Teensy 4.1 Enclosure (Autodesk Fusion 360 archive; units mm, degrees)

design "Teensy 4.1 Enclosure" references "Teensy 4.1 Modell"
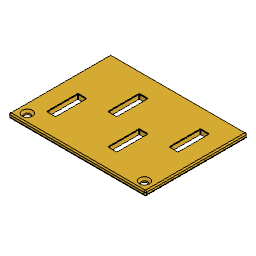
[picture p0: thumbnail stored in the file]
description: STEP AP214
part number: Teensy_4.1_Assembly_simplified
parameter "adsk_nheig" = 1.8
parameter "adsk_maxdia" = 6.3525
parameter "adsk_nomdia" = 3
parameter "adsk_waflat" = 5.5
parameter "adsk_chamang1" = 30
parameter "adsk_chamang2" = 30
parameter "adsk_beardia" = 5.39
parameter "adsk_nheig_1" = 1.8
parameter "adsk_maxdia_1" = 6.3525
parameter "adsk_nomdia_1" = 3
parameter "adsk_waflat_1" = 5.5
parameter "adsk_chamang1_1" = 30
parameter "adsk_chamang2_1" = 30
parameter "adsk_beardia_1" = 5.39
external_derived "Extern abgeleitet" bodies "Teensy 4.1"
move "Verschieben2"
move "Verschieben3" TranslateX 0 TranslateY 24 TranslateZ 3
sketch "Skizze6" plane through (0, 0, 0) normal (0, 0, 1) x axis (1, 0, 0)
  line L1 (65, 50) -> (-2, 50)
  line L2 (65, 0) -> (65, 50)
  line L3 (-2, 0) -> (65, 0)
  line L4 (-2, 50) -> (-2, 0)
  horizontal L1
  vertical L2
  horizontal L3
  vertical L4
extrude "Extrusion4" new body sketch "Skizze6" along normal blind 12
fillet "Abrundung4" radius 0.6
work_plane "Arbeitsebene" AlongDistance -2.5
split "Teilen"
shell "Schale" innerThickness 2
fillet "Abrundung5" radius 0.5
sketch "Skizze7" plane through (65, 0, 0) normal (1, 0, 0) x axis (0, 1, 0)
  line L1 (0.6, 9.5) -> (49.4, 9.5)
  line L2 (0.6, 0.6) -> (0.6, 9.5)
  line L3 (49.4, 0.6) -> (0.6, 0.6)
  line L4 (49.4, 9.5) -> (49.4, 0.6)
  line L5 (43.7841, 7.2878) -> (29.7841, 7.2878)
  line L6 (43.7841, 4.2878) -> (43.7841, 7.2878)
  line L7 (29.7841, 4.2878) -> (43.7841, 4.2878)
  line L8 (29.7841, 7.2878) -> (29.7841, 4.2878)
  horizontal L5
  vertical L6
  horizontal L7
  vertical L8
sketch "Skizze8" plane through (65, 0, 0) normal (1, 0, 0) x axis (0, 1, 0)
  line L1 (0.6, 9.5) -> (49.4, 9.5)
  line L2 (0.6, 0.6) -> (0.6, 9.5)
  line L3 (49.4, 0.6) -> (0.6, 0.6)
  line L4 (49.4, 9.5) -> (49.4, 0.6)
  line L5 (44.2751, 7.4459) -> (29.7875, 7.4459)
  line L6 (44.2751, 4.2911) -> (44.2751, 7.4459)
  line L7 (29.7875, 4.2911) -> (44.2751, 4.2911)
  line L8 (29.7875, 7.4459) -> (29.7875, 4.2911)
  horizontal L5
  vertical L6
  horizontal L7
  vertical L8
extrude "Extrusion6" cut sketch "Skizze8" profile of L5 L6 L7 L8 against normal blind 3
fillet "Abrundung7" radius 0.2
sketch "Skizze9" plane through (-2, 0, 0) normal (-1, 0, 0) x axis (0, -1, 0)
  line L1 (-50, 9.5) -> (-0.6, 9.5)
  line L2 (-50, 0.6) -> (-50, 9.5)
  line L3 (-0.6, 0.6) -> (-50, 0.6)
  line L4 (-0.6, 9.5) -> (-0.6, 0.6)
  line L5 (-31.9719, 7.9619) -> (-41.6044, 7.9619)
  line L6 (-31.9719, 3.7343) -> (-31.9719, 7.9619)
  line L7 (-41.6044, 3.7343) -> (-31.9719, 3.7343)
  line L8 (-41.6044, 7.9619) -> (-41.6044, 3.7343)
  horizontal L5
  vertical L6
  horizontal L7
  vertical L8
extrude "Extrusion7" cut sketch "Skizze9" profile of L5 L6 L7 L8 against normal blind 3
fillet "Abrundung8" radius 0.2
move "Verschieben4" TranslateX 0 TranslateY 0 TranslateZ -0.8
combine "Kombinieren2"
sketch "Skizze10" plane through (0, 0, 9.5) normal (0, 0, 1) x axis (-1, 0, 0)
  line L1 (-62.5, -48.5) -> (-0.5, -48.5)
  line L2 (-63.5, -2.5) -> (-63.5, -47.5)
  line L3 (-0.5, -1.5) -> (-62.5, -1.5)
  line L4 (0.5, -47.5) -> (0.5, -2.5)
  line L5 (1.8, -0.6) -> (1.8, -49.8)
  line L6 (-64.4, -0.2) -> (1.4, -0.2)
  line L7 (-64.8, -49.4) -> (-64.8, -0.6)
  line L8 (1.8, -49.8) -> (-64.4, -49.8)
  line L9 (0.5, -1.5) -> (-8.0206, -1.5)
  line L10 (0.5, -8.5367) -> (0.5, -1.5)
  line L11 (-8.0206, -8.5367) -> (0.5, -8.5367)
  line L12 (-8.0206, -1.5) -> (-8.0206, -8.5367)
  line L13 (-63.5206, -8.5367) -> (-55, -8.5367)
  line L14 (-63.5206, -1.5) -> (-63.5206, -8.5367)
  line L15 (-55, -1.5) -> (-63.5206, -1.5)
  line L16 (-55, -8.5367) -> (-55, -1.5)
  arc A1 centre (-0.5, -47.5) radius 1 clockwise from (0.5, -47.5) to (-0.5, -48.5)
  arc A2 centre (-62.5, -47.5) radius 1 clockwise from (-62.5, -48.5) to (-63.5, -47.5)
  arc A3 centre (-62.5, -2.5) radius 1 clockwise from (-63.5, -2.5) to (-62.5, -1.5)
  arc A4 centre (-0.5, -2.5) radius 1 clockwise from (-0.5, -1.5) to (0.5, -2.5)
  arc A5 centre (1.4, -0.6) radius 0.4 clockwise from (1.4, -0.2) to (1.8, -0.6)
  arc A6 centre (-64.4, -0.6) radius 0.4 clockwise from (-64.8, -0.6) to (-64.4, -0.2)
  arc A7 centre (-64.4, -49.4) radius 0.4 clockwise from (-64.4, -49.8) to (-64.8, -49.4)
  point P26 (0.5, -8.5367)
  point P24 (-8.0206, -1.5)
  horizontal L9
  vertical L10
  horizontal L11
  vertical L12
  coincident L4 P26
  coincident L3 P24
  horizontal L15
  vertical L16
  horizontal L13
  vertical L14
extrude "Extrusion8" add sketch "Skizze10" profile of L2 A3 L3 A4 L4 L9 L10 L11 L12 L13 L15 L16 against normal blind 9.2
fillet "Abrundung9" radius 0.2
hole "Bohrung2" HoleDepth 15 HoleDiameter 3 TipAngle 180 CSDiameter 6 CSAngle 90 RefDim1 5 RefDim2 4
hole "Bohrung3" HoleDepth 15 HoleDiameter 3 TipAngle 180 CSDiameter 6 CSAngle 90 RefDim1 4 RefDim2 5
sketch "Skizze12" plane through (0, 0, 0) normal (0, 0, -1) x axis (1, 0, 0)
  line L1 (-1.4, -0.6) -> (64.4, -0.6)
  line L2 (-1.4, -49.4) -> (-1.4, -0.6)
  line L3 (64.4, -49.4) -> (-1.4, -49.4)
  line L4 (64.4, -0.6) -> (64.4, -49.4)
  line L5 (60.1995, -7.5699) -> (57.3998, -5.9529)
  line L6 (62.9998, -5.9537) -> (60.1995, -7.5699)
  line L7 (63.0002, -2.7206) -> (62.9998, -5.9537)
  line L8 (60.2005, -1.1036) -> (63.0002, -2.7206)
  line L9 (57.4002, -2.7197) -> (60.2005, -1.1036)
  line L10 (57.3998, -5.9529) -> (57.4002, -2.7197)
  circle C1 centre (60.2, -4.3367) radius 1.5
  circle C2 centre (2.8206, -4.3367) radius 1.5
  point P2 (60.2, -4.3367)
  point P14 (60.2, -4.3367)
  coincident P2 P14
  dimension "d77" distance P14 L10 = 2.8
extrude "Extrusion9" cut sketch "Skizze12" profile of C1 L5 L6 L7 L8 L9 L10 against normal blind 2.4
sketch "Skizze13" plane through (0, 0, 0) normal (0, 0, -1) x axis (1, 0, 0)
  line L1 (57.3998, -5.9529) -> (60.1995, -7.5699)
  line L2 (57.4002, -2.7197) -> (57.3998, -5.9529)
  line L3 (60.2005, -1.1036) -> (57.4002, -2.7197)
  line L4 (63.0002, -2.7206) -> (60.2005, -1.1036)
  line L5 (62.9998, -5.9537) -> (63.0002, -2.7206)
  line L6 (60.1995, -7.5699) -> (62.9998, -5.9537)
  line L7 (-1.4, -0.6) -> (64.4, -0.6)
  line L8 (-1.4, -49.4) -> (-1.4, -0.6)
  line L9 (64.4, -49.4) -> (-1.4, -49.4)
  line L10 (64.4, -0.6) -> (64.4, -49.4)
  line L11 (0.0214, -5.9546) -> (0.0199, -2.7214)
  line L12 (2.8221, -7.5699) -> (0.0214, -5.9546)
  line L13 (5.6214, -5.952) -> (2.8221, -7.5699)
  line L14 (5.6199, -2.7189) -> (5.6214, -5.952)
  line L15 (2.8192, -1.1036) -> (5.6199, -2.7189)
  line L16 (0.0199, -2.7214) -> (2.8192, -1.1036)
  circle C1 centre (2.8206, -4.3367) radius 1.5
  point P8 (2.8206, -4.3367)
  point P19 (2.8206, -4.3367)
  coincident P8 P19
  dimension "d80" distance P19 L16 = 2.8
extrude "Extrusion10" cut sketch "Skizze13" profile of C1 L11 L12 L13 L14 L15 L16 against normal blind 2.4
delete_face "Fläche löschen1"
delete_face "Fläche löschen2"
fillet "Abrundung10" radius 0.1
fillet "Abrundung11" radius 0.1
sketch "Skizze14" plane through (0, 0, 2) normal (0, 0, 1) x axis (-1, 0, 0)
  line L1 (-8.2206, -2.5) -> (-8.2206, -8.3367)
  line L2 (-54.8, -2.5) -> (-8.2206, -2.5)
  line L3 (-54.8, -8.3367) -> (-54.8, -2.5)
  line L4 (-62.5, -8.7367) -> (-55.2, -8.7367)
  line L5 (-62.5, -47.5) -> (-62.5, -8.7367)
  line L6 (-0.5, -47.5) -> (-62.5, -47.5)
  line L7 (-0.5, -8.7367) -> (-0.5, -47.5)
  line L8 (-7.8206, -8.7367) -> (-0.5, -8.7367)
  line L9 (-1, -27) -> (-62, -27)
  line L10 (-1, -30) -> (-1, -27)
  line L11 (-62, -30) -> (-1, -30)
  line L12 (-62, -27) -> (-62, -30)
  line L13 (-1, -46.6249) -> (-62, -46.6249)
  line L14 (-1, -44) -> (-1, -46.6249)
  line L15 (-62, -44) -> (-1, -44)
  line L16 (-62, -46.6249) -> (-62, -44)
  arc A1 centre (-55.2, -8.3367) radius 0.4 clockwise from (-54.8, -8.3367) to (-55.2, -8.7367)
  arc A2 centre (-7.8206, -8.3367) radius 0.4 clockwise from (-7.8206, -8.7367) to (-8.2206, -8.3367)
  horizontal L9
  vertical L10
  horizontal L11
  vertical L12
  horizontal L13
  vertical L14
  horizontal L15
  vertical L16
extrude "Extrusion11" new body sketch "Skizze14" profile of L9 L10 L11 L12 L13 L14 L15 L16 along normal blind 1
fillet "Abrundung12" radius 0.1
sketch "Skizze15" plane through (0, 0, 2) normal (0, 0, 1) x axis (-1, 0, 0)
  line L1 (-8.2206, -2.5) -> (-8.2206, -8.3367)
  line L2 (-54.8, -2.5) -> (-8.2206, -2.5)
  line L3 (-54.8, -8.3367) -> (-54.8, -2.5)
  line L4 (-62.5, -8.7367) -> (-55.2, -8.7367)
  line L5 (-62.5, -47.5) -> (-62.5, -8.7367)
  line L6 (-0.5, -47.5) -> (-62.5, -47.5)
  line L7 (-0.5, -8.7367) -> (-0.5, -47.5)
  line L8 (-7.8206, -8.7367) -> (-0.5, -8.7367)
  curve K1
  curve K2
  curve K3
  curve K4
  arc A1 centre (-55.2, -8.3367) radius 0.4 clockwise from (-54.8, -8.3367) to (-55.2, -8.7367)
  arc A2 centre (-7.8206, -8.3367) radius 0.4 clockwise from (-7.8206, -8.7367) to (-8.2206, -8.3367)
  dimension "d92" Text1-Height = 4
  dimension "d93" Text = 0 (= "Text1-Text")
extrude "Extrusion12" add sketch "Skizze15" along normal blind 0.2
sketch "Skizze16" plane through (0, 0, 2.4) normal (0, 0, -1) x axis (1, 0, 0)
  line L1 (0.0199, -2.7214) -> (2.8192, -1.1036)
  line L2 (0.0214, -5.9546) -> (0.0199, -2.7214)
  line L3 (2.8221, -7.5699) -> (0.0214, -5.9546)
  line L4 (5.6214, -5.952) -> (2.8221, -7.5699)
  line L5 (5.6199, -2.7189) -> (5.6214, -5.952)
  line L6 (2.8192, -1.1036) -> (5.6199, -2.7189)
  circle C1 centre (2.8206, -4.3367) radius 1.5
  circle C2 centre (2.8206, -4.3367) radius 1.5
  concentric C1 C2
extrude "Extrusion13" cut sketch "Skizze16" profile of C1 C2 against normal blind 16
sketch "Skizze17" plane through (0, 0, 2.4) normal (0, 0, -1) x axis (1, 0, 0)
  line L1 (57.3998, -5.9529) -> (57.4002, -2.7197)
  line L2 (60.1995, -7.5699) -> (57.3998, -5.9529)
  line L3 (62.9998, -5.9537) -> (60.1995, -7.5699)
  line L4 (63.0002, -2.7206) -> (62.9998, -5.9537)
  line L5 (60.2005, -1.1036) -> (63.0002, -2.7206)
  line L6 (57.4002, -2.7197) -> (60.2005, -1.1036)
  circle C1 centre (60.2, -4.3367) radius 1.5
  circle C2 centre (60.2, -4.3367) radius 1.5
  concentric C1 C2
extrude "Extrusion14" cut sketch "Skizze17" profile of C1 C2 against normal blind 12
chamfer "Fase1" distance 1
chamfer "Fase2" distance 1
sketch "Skizze18" plane through (0, 0, 11.2) normal (0, 0, 1) x axis (-1, 0, 0)
  line L1 (-64.4, -49.4) -> (-64.4, -0.6)
  line L2 (1.4, -49.4) -> (-64.4, -49.4)
  line L3 (1.4, -0.6) -> (1.4, -49.4)
  line L4 (-64.4, -0.6) -> (1.4, -0.6)
  line L5 (-52, -25) -> (-56, -25)
  line L6 (-52, -40) -> (-52, -25)
  line L7 (-56, -40) -> (-52, -40)
  line L8 (-56, -25) -> (-56, -40)
  line L9 (-37, -10) -> (-41, -10)
  line L10 (-37, -25) -> (-37, -10)
  line L11 (-41, -25) -> (-37, -25)
  line L12 (-41, -10) -> (-41, -25)
  line L13 (-22, -25) -> (-26, -25)
  line L14 (-22, -40) -> (-22, -25)
  line L15 (-26, -40) -> (-22, -40)
  line L16 (-26, -25) -> (-26, -40)
  line L17 (-7, -10) -> (-11, -10)
  line L18 (-7, -25) -> (-7, -10)
  line L19 (-11, -25) -> (-7, -25)
  line L20 (-11, -10) -> (-11, -25)
  circle C1 centre (-2.8206, -4.3367) radius 2.5
  circle C2 centre (-60.2, -4.3367) radius 2.5
  horizontal L5
  vertical L6
  horizontal L7
  vertical L8
  horizontal L9
  vertical L10
  horizontal L11
  vertical L12
  horizontal L13
  vertical L14
  horizontal L15
  vertical L16
  horizontal L17
  vertical L18
  horizontal L19
  vertical L20
extrude "Extrusion15" cut sketch "Skizze18" profile of L5 L6 L7 L8 L9 L10 L11 L12 L13 L14 L15 L16 L17 L18 L19 L20 against normal blind 8
fillet "Abrundung13" radius 0.2
fillet "Abrundung14" radius 0.2
sketch "Skizze19" plane through (65, 0, 0) normal (1, 0, 0) x axis (0, 1, 0)
  line L1 (0.6, 9.3) -> (49.4, 9.3)
  line L2 (0.6, 0.6) -> (0.6, 9.3)
  line L3 (49.4, 0.6) -> (0.6, 0.6)
  line L4 (49.4, 9.3) -> (49.4, 0.6)
  line L5 (44.0751, 7.6459) -> (29.9875, 7.6459)
  line L6 (44.4751, 4.4911) -> (44.4751, 7.2459)
  line L7 (29.9875, 4.0911) -> (44.0751, 4.0911)
  line L8 (29.5875, 7.2459) -> (29.5875, 4.4911)
  arc A1 centre (29.9875, 7.2459) radius 0.4 clockwise from (29.5875, 7.2459) to (29.9875, 7.6459)
  arc A2 centre (44.0751, 7.2459) radius 0.4 clockwise from (44.0751, 7.6459) to (44.4751, 7.2459)
  arc A3 centre (44.0751, 4.4911) radius 0.4 clockwise from (44.4751, 4.4911) to (44.0751, 4.0911)
  arc A4 centre (29.9875, 4.4911) radius 0.4 clockwise from (29.9875, 4.0911) to (29.5875, 4.4911)
sketch "Skizze20" plane through (65, 0, 0) normal (1, 0, 0) x axis (0, 1, 0)
  line L1 (17, 12) -> (12, 12)
  line L2 (17, 4) -> (17, 12)
  line L3 (13, 3) -> (16, 3)
  line L4 (12, 12) -> (12, 4)
  arc A1 centre (13, 4) radius 1 clockwise from (13, 3) to (12, 4)
  arc A2 centre (16, 4) radius 1 clockwise from (17, 4) to (16, 3)
  horizontal L1
  vertical L2
  horizontal L3
  vertical L4
  tangent L4 A1
  tangent L3 A1
  tangent L2 A2
  tangent L3 A2
  equal A1 A2
  dimension "d108" radius A1 = 1
extrude "Extrusion16" cut sketch "Skizze20" against normal blind 9
fillet "Abrundung15" radius 0.2
combine "Kombinieren3"
combine "Kombinieren4"
offset_faces "Flächen versetzen1" distance 2
offset_faces "Flächen versetzen2" distance 1.3
sketch "Skizze21" plane through (0, 0, 8.7) normal (0, 0, -1) x axis (1, 0, 0)
  line L1 (25.8, -24.8) -> (22.2, -24.8)
  line L2 (26.2, -39.8) -> (26.2, -25.2)
  line L3 (22.2, -40.2) -> (25.8, -40.2)
  line L4 (21.8, -25.2) -> (21.8, -39.8)
  line L5 (55.8, -24.8) -> (52.2, -24.8)
  line L6 (56.2, -39.8) -> (56.2, -25.2)
  line L7 (52.2, -40.2) -> (55.8, -40.2)
  line L8 (51.8, -25.2) -> (51.8, -39.8)
  line L9 (6.8, -10.2) -> (6.8, -24.8)
  line L10 (10.8, -9.8) -> (7.2, -9.8)
  line L11 (11.2, -24.8) -> (11.2, -10.2)
  line L12 (7.2, -25.2) -> (10.8, -25.2)
  line L13 (40.8, -9.8) -> (37.2, -9.8)
  line L14 (41.2, -24.8) -> (41.2, -10.2)
  line L15 (37.2, -25.2) -> (40.8, -25.2)
  line L16 (36.8, -10.2) -> (36.8, -24.8)
  line L17 (8.0206, -8.3367) -> (8.0206, -2.2)
  line L18 (0.2, -8.5367) -> (7.8206, -8.5367)
  line L19 (0, -47.5) -> (0, -8.7367)
  line L20 (62.5, -48) -> (0.5, -48)
  line L21 (63, -8.7367) -> (63, -47.5)
  line L22 (55.2, -8.5367) -> (62.8, -8.5367)
  line L23 (55, -2.2) -> (55, -8.3367)
  line L24 (8.2206, -2) -> (54.8, -2)
  line L25 (38, -44) -> (27, -44)
  line L26 (38, -48) -> (38, -44)
  line L27 (27, -48) -> (38, -48)
  line L28 (27, -44) -> (27, -48)
  arc A1 centre (22.2, -25.2) radius 0.4 clockwise from (21.8, -25.2) to (22.2, -24.8)
  arc A2 centre (25.8, -25.2) radius 0.4 clockwise from (25.8, -24.8) to (26.2, -25.2)
  arc A3 centre (25.8, -39.8) radius 0.4 clockwise from (26.2, -39.8) to (25.8, -40.2)
  arc A4 centre (22.2, -39.8) radius 0.4 clockwise from (22.2, -40.2) to (21.8, -39.8)
  arc A5 centre (52.2, -25.2) radius 0.4 clockwise from (51.8, -25.2) to (52.2, -24.8)
  arc A6 centre (55.8, -25.2) radius 0.4 clockwise from (55.8, -24.8) to (56.2, -25.2)
  arc A7 centre (55.8, -39.8) radius 0.4 clockwise from (56.2, -39.8) to (55.8, -40.2)
  arc A8 centre (52.2, -39.8) radius 0.4 clockwise from (52.2, -40.2) to (51.8, -39.8)
  arc A9 centre (7.2, -24.8) radius 0.4 clockwise from (7.2, -25.2) to (6.8, -24.8)
  arc A10 centre (7.2, -10.2) radius 0.4 clockwise from (6.8, -10.2) to (7.2, -9.8)
  arc A11 centre (10.8, -10.2) radius 0.4 clockwise from (10.8, -9.8) to (11.2, -10.2)
  arc A12 centre (10.8, -24.8) radius 0.4 clockwise from (11.2, -24.8) to (10.8, -25.2)
  arc A13 centre (37.2, -10.2) radius 0.4 clockwise from (36.8, -10.2) to (37.2, -9.8)
  arc A14 centre (40.8, -10.2) radius 0.4 clockwise from (40.8, -9.8) to (41.2, -10.2)
  arc A15 centre (40.8, -24.8) radius 0.4 clockwise from (41.2, -24.8) to (40.8, -25.2)
  arc A16 centre (37.2, -24.8) radius 0.4 clockwise from (37.2, -25.2) to (36.8, -24.8)
  arc A17 centre (8.2206, -2.2) radius 0.2 clockwise from (8.0206, -2.2) to (8.2206, -2)
  arc A18 centre (7.8206, -8.3367) radius 0.2 clockwise from (8.0206, -8.3367) to (7.8206, -8.5367)
  arc A19 centre (0.2, -8.7367) radius 0.2 clockwise from (0, -8.7367) to (0.2, -8.5367)
  arc A20 centre (0.5, -47.5) radius 0.5 clockwise from (0.5, -48) to (0, -47.5)
  arc A21 centre (62.5, -47.5) radius 0.5 clockwise from (63, -47.5) to (62.5, -48)
  arc A22 centre (62.8, -8.7367) radius 0.2 clockwise from (62.8, -8.5367) to (63, -8.7367)
  arc A23 centre (55.2, -8.3367) radius 0.2 clockwise from (55.2, -8.5367) to (55, -8.3367)
  arc A24 centre (54.8, -2.2) radius 0.2 clockwise from (54.8, -2) to (55, -2.2)
  point P76 (38, -48)
  horizontal L25
  vertical L26
  horizontal L27
  vertical L28
  coincident L20 P76
extrude "Extrusion17" add sketch "Skizze21" profile of L20 L25 L26 L27 L28 along normal blind 1
draft "Verjüngung" Angle1 10 Angle2 0
delete_face "Fläche löschen3"
delete_face "Fläche löschen4"
delete_face "Fläche löschen5"
delete_face "Fläche löschen6"
delete_face "Fläche löschen7"
delete_face "Fläche löschen8"
delete_face "Fläche löschen9"
delete_face "Fläche löschen10"
delete_face "Fläche löschen11"
fillet "Abrundung16" radius 0.2
delete_face "Fläche löschen12"
fillet "Abrundung17" radius 0.2
delete_face "Fläche löschen13"
delete_face "Fläche löschen14"
fillet "Abrundung18" radius 0.2
delete_face "Fläche löschen15"
move_face "Fläche verschieben"
sketch "Skizze22" plane through (0, 48, 0) normal (0, 1, 0) x axis (-1, 0, 0)
  line L1 (-62.5, 9.5) -> (-0.5, 9.5)
  line L2 (-62.5, 8.7) -> (-62.5, 9.5)
  line L3 (-38, 8.7) -> (-62.5, 8.7)
  line L4 (-38, 8.0101) -> (-38, 8.7)
  line L5 (-27, 8.0101) -> (-38, 8.0101)
  line L6 (-27, 8.7) -> (-27, 8.0101)
  line L7 (-0.5, 8.7) -> (-27, 8.7)
  line L8 (-0.5, 9.5) -> (-0.5, 8.7)
  line L9 (-27, 8.7) -> (-38, 8.7)
  line L10 (-27, 8.0101) -> (-27, 8.7)
  line L11 (-38, 8.0101) -> (-27, 8.0101)
  line L12 (-38, 8.7) -> (-38, 8.0101)
  point P7 (-27, 8.0101)
  point P12 (-27, 8.0101)
  point P5 (-38, 8.7)
  point P10 (-38, 8.7)
  horizontal L9
  vertical L10
  horizontal L11
  vertical L12
  coincident P7 P12
  coincident P5 P10
extrude "Extrusion18" add sketch "Skizze22" profile of L4 L5 L6 L9 L10 L11 L12 along normal blind 0.9
fillet "Abrundung19" radius 0.1
chamfer "Fase3" distance 0.1 distance 0.5
fillet "Abrundung20" radius 0.1
sketch "Skizze23" plane through (0, 0, 3) normal (0, 0, 1) x axis (-1, 0, 0)
  line L1 (-63, -29.9) -> (-63, -27.1)
  line L2 (-1.1, -29.9) -> (-63, -29.9)
  line L3 (-1.1, -27.1) -> (-1.1, -29.9)
  line L4 (-63, -27.1) -> (-1.1, -27.1)
  line L5 (-61.8, -27.1) -> (-63, -27.1)
  line L6 (-61.8, -29.9) -> (-61.8, -27.1)
  line L7 (-63, -29.9) -> (-61.8, -29.9)
  line L8 (-63, -27.1) -> (-63, -29.9)
  point P2 (-63, -27.1)
  point P6 (-63, -27.1)
  point P7 (-61.8, -27.1)
  horizontal L5
  vertical L6
  horizontal L7
  vertical L8
  coincident P2 P6
  dimension "d134" distance P6 P7 = 1.2
extrude "Extrusion19" add sketch "Skizze23" profile of L1 L2 L4 L5 L6 L7 L8 along normal blind 5
fillet "Abrundung21" radius 0.4
delete_face "Fläche löschen16"
delete_face "Fläche löschen17"
delete_face "Fläche löschen18"
extrude "Extrusion20" add of existing geometry blind 1.3
extrude "Extrusion21" add of existing geometry blind 2
move "Verschieben5"
delete_face "Fläche löschen19"
delete_face "Fläche löschen20"
delete_face "Fläche löschen21"
delete_face "Fläche löschen22"
extrude "Extrusion22" add of existing geometry blind 0.5
sketch "Skizze24" plane through (0, 0, 3) normal (0, 0, 1) x axis (-1, 0, 0)
  line L1 (-63, -44) -> (0, -44)
  line L2 (-63, -47.5) -> (-63, -44)
  line L3 (-0.5, -48) -> (-62.5, -48)
  line L4 (0, -44) -> (0, -47.5)
  line L5 (-61.3, -44) -> (-63, -44)
  line L6 (-61.3, -48) -> (-61.3, -44)
  line L7 (-63, -48) -> (-61.3, -48)
  line L8 (-63, -44) -> (-63, -48)
  arc A1 centre (-62.5, -47.5) radius 0.5 clockwise from (-62.5, -48) to (-63, -47.5)
  arc A2 centre (-0.5, -47.5) radius 0.5 clockwise from (0, -47.5) to (-0.5, -48)
  point P3 (-63, -44)
  point P10 (-63, -44)
  point P11 (-61.3, -44)
  horizontal L5
  vertical L6
  horizontal L7
  vertical L8
  coincident P3 P10
  dimension "d145" distance P10 P11 = 1.7
extrude "Extrusion23" add sketch "Skizze24" profile of L1 L2 A1 L3 L5 L6 L7 L8 along normal blind 5
delete_face "Fläche löschen23"
delete_face "Fläche löschen24"
delete_face "Fläche löschen25"
delete_face "Fläche löschen26"
extrude "Extrusion24" add of existing geometry blind 0.3
extrude "Extrusion25" add of existing geometry blind 0.4
delete_face "Fläche löschen27"
extrude "Extrusion26" add of existing geometry blind 0.7
delete_face "Fläche löschen28"
delete_face "Fläche löschen29"
delete_face "Fläche löschen30"
delete_face "Fläche löschen31"
fillet "Abrundung22" radius 0.2
fillet "Abrundung23" radius 0.2
fillet "Abrundung24" radius 0.1
delete_face "Fläche löschen32"
fillet "Abrundung25" radius 0.2
delete_face "Fläche löschen33"
fillet "Abrundung26" radius 0.2
fillet "Abrundung27" radius 0.2
delete_face "Fläche löschen34"
delete_face "Fläche löschen35"
delete_face "Fläche löschen36"
delete_face "Fläche löschen37"
extrude "Extrusion27" cut of existing geometry blind -0.1
extrude "Extrusion28" add of existing geometry blind 0.4
extrude "Extrusion29" add of existing geometry blind 0.5
delete_face "Fläche löschen38"
extrude "Extrusion30" add of existing geometry blind 1.6
extrude "Extrusion31" add of existing geometry blind 1
sketch "Skizze25" plane through (0, 0, 3) normal (0, 0, 1) x axis (-1, 0, 0)
  line L1 (-61.3, -29.9) -> (-61.3, -25.6)
  line L2 (0, -29.9) -> (-61.3, -29.9)
  line L3 (0, -25.6) -> (0, -29.9)
  line L4 (-61.3, -25.6) -> (0, -25.6)
  line L5 (-58.5, -25.6) -> (-61.3, -25.6)
  line L6 (-58.5, -27.5) -> (-58.5, -25.6)
  line L7 (-61.3, -27.5) -> (-58.5, -27.5)
  line L8 (-61.3, -25.6) -> (-61.3, -27.5)
  point P2 (-61.3, -25.6)
  point P6 (-61.3, -25.6)
  horizontal L5
  vertical L6
  horizontal L7
  vertical L8
  coincident P2 P6
extrude "Extrusion32" add sketch "Skizze25" profile of L1 L4 L5 L6 L7 L8 along normal blind 5
extrude "Extrusion33" add of existing geometry blind 9
sketch "Skizze26" plane through (0, 0, 3) normal (0, 0, 1) x axis (-1, 0, 0)
  line L1 (-49.5, -27.5) -> (-49.5, -25.6)
  line L2 (-61.3, -27.5) -> (-49.5, -27.5)
  line L3 (-61.3, -29.9) -> (-61.3, -27.5)
  line L4 (0, -29.9) -> (-61.3, -29.9)
  line L5 (0, -25.6) -> (0, -29.9)
  line L6 (-49.5, -25.6) -> (0, -25.6)
  line L7 (-4, -25.6) -> (0, -25.6)
  line L8 (-4, -27.5) -> (-4, -25.6)
  line L9 (0, -27.5) -> (-4, -27.5)
  line L10 (0, -25.6) -> (0, -27.5)
  point P7 (0, -25.6)
  point P8 (0, -25.6)
  point P9 (-4, -25.6)
  point P11 (0, -27.5)
  horizontal L7
  vertical L8
  horizontal L9
  vertical L10
  coincident P7 P8
  dimension "d180" distance P8 P9 = 4
  dimension "d181" distance P8 P11 = 1.9
extrude "Extrusion34" add sketch "Skizze26" profile of L5 L6 L7 L8 L9 L10 along normal blind 5
sketch "Skizze27" plane through (0, 0, 0) normal (1, 0, 0) x axis (0, 1, 0)
  line L1 (41.4044, 8.1619) -> (32.1719, 8.1619)
  line L2 (41.8044, 3.9343) -> (41.8044, 7.7619)
  line L3 (32.1719, 3.5343) -> (41.4044, 3.5343)
  line L4 (31.7719, 7.7619) -> (31.7719, 3.9343)
  line L5 (25.6, 8) -> (25.6, 2.5)
  line L6 (27.5, 8) -> (25.6, 8)
  line L7 (27.5, 3) -> (27.5, 8)
  line L8 (29.9, 3) -> (27.5, 3)
  line L9 (29.9, 2.5) -> (29.9, 3)
  line L10 (43.9, 2.5) -> (29.9, 2.5)
  line L11 (43.9, 2.9) -> (43.9, 2.5)
  curve K1 (44.0732, 3) -> (43.9, 2.9)
  line L12 (47.5, 3) -> (44.0732, 3)
  line L13 (47.5, 9) -> (47.5, 3)
  line L14 (8.7367, 9) -> (47.5, 9)
  line L15 (8.7367, 2.5) -> (8.7367, 9)
  line L16 (25.6, 2.5) -> (8.7367, 2.5)
  line L17 (31, 8) -> (27.5, 8)
  line L18 (31, 5) -> (31, 8)
  line L19 (27.5, 5) -> (31, 5)
  line L20 (27.5, 8) -> (27.5, 5)
  line L21 (48, 8) -> (42.5, 8)
  line L22 (48, 5) -> (48, 8)
  line L23 (42.5, 5) -> (48, 5)
  line L24 (42.5, 8) -> (42.5, 5)
  arc A1 centre (32.1719, 7.7619) radius 0.4 clockwise from (31.7719, 7.7619) to (32.1719, 8.1619)
  arc A2 centre (41.4044, 7.7619) radius 0.4 clockwise from (41.4044, 8.1619) to (41.8044, 7.7619)
  arc A3 centre (41.4044, 3.9343) radius 0.4 clockwise from (41.8044, 3.9343) to (41.4044, 3.5343)
  arc A4 centre (32.1719, 3.9343) radius 0.4 clockwise from (32.1719, 3.5343) to (31.7719, 3.9343)
  point P16 (27.5, 8)
  point P27 (27.5, 8)
  horizontal L17
  vertical L18
  horizontal L19
  vertical L20
  coincident P16 P27
  horizontal L21
  vertical L22
  horizontal L23
  vertical L24
extrude "Extrusion35" add sketch "Skizze27" profile of L7 L13 L17 L18 L19 L20 L21 L23 L24 along normal blind 4
extrude "Extrusion36" cut of existing geometry blind -1
fillet "Abrundung28" radius 0.3
fillet "Abrundung29" radius 0.2
offset_faces "Flächen versetzen3" distance -0.1
offset_faces "Flächen versetzen4" distance -0.1
combine "Kombinieren5"
sketch "Skizze28" plane through (0, 0, 8.7) normal (0, 0, -1) x axis (1, 0, 0)
  line L1 (27, -47.9) -> (0.5, -47.9)
  line L2 (27, -44.0875) -> (27, -47.9)
  line L3 (38, -44.0875) -> (27, -44.0875)
  line L4 (38, -47.9) -> (38, -44.0875)
  line L5 (62.5, -47.9) -> (38, -47.9)
  line L6 (62.9, -8.7367) -> (62.9, -47.5)
  line L7 (55.2, -8.6367) -> (62.8, -8.6367)
  line L8 (54.9, -2.2) -> (54.9, -8.3367)
  line L9 (8.2206, -2.1) -> (54.8, -2.1)
  line L10 (8.1206, -8.3367) -> (8.1206, -2.2)
  line L11 (0.2, -8.6367) -> (7.8206, -8.6367)
  line L12 (0.1, -47.5) -> (0.1, -8.7367)
  line L13 (25.8, -24.8) -> (22.2, -24.8)
  line L14 (26.2, -39.8) -> (26.2, -25.2)
  line L15 (22.2, -40.2) -> (25.8, -40.2)
  line L16 (21.8, -25.2) -> (21.8, -39.8)
  line L17 (55.8, -24.8) -> (52.2, -24.8)
  line L18 (56.2, -39.8) -> (56.2, -25.2)
  line L19 (52.2, -40.2) -> (55.8, -40.2)
  line L20 (51.8, -25.2) -> (51.8, -39.8)
  line L21 (6.8, -10.2) -> (6.8, -24.8)
  line L22 (10.8, -9.8) -> (7.2, -9.8)
  line L23 (11.2, -24.8) -> (11.2, -10.2)
  line L24 (7.2, -25.2) -> (10.8, -25.2)
  line L25 (40.8, -9.8) -> (37.2, -9.8)
  line L26 (41.2, -24.8) -> (41.2, -10.2)
  line L27 (37.2, -25.2) -> (40.8, -25.2)
  line L28 (36.8, -10.2) -> (36.8, -24.8)
  line L29 (58, -41) -> (61, -41)
  line L30 (58, -32) -> (58, -41)
  line L31 (61, -32) -> (58, -32)
  line L32 (61, -41) -> (61, -32)
  arc A1 centre (62.5, -47.5) radius 0.4 clockwise from (62.9, -47.5) to (62.5, -47.9)
  arc A2 centre (62.8, -8.7367) radius 0.1 clockwise from (62.8, -8.6367) to (62.9, -8.7367)
  arc A3 centre (55.2, -8.3367) radius 0.3 clockwise from (55.2, -8.6367) to (54.9, -8.3367)
  arc A4 centre (54.8, -2.2) radius 0.1 clockwise from (54.8, -2.1) to (54.9, -2.2)
  arc A5 centre (8.2206, -2.2) radius 0.1 clockwise from (8.1206, -2.2) to (8.2206, -2.1)
  arc A6 centre (7.8206, -8.3367) radius 0.3 clockwise from (8.1206, -8.3367) to (7.8206, -8.6367)
  arc A7 centre (0.2, -8.7367) radius 0.1 clockwise from (0.1, -8.7367) to (0.2, -8.6367)
  arc A8 centre (0.5, -47.5) radius 0.4 clockwise from (0.5, -47.9) to (0.1, -47.5)
  arc A9 centre (22.2, -25.2) radius 0.4 clockwise from (21.8, -25.2) to (22.2, -24.8)
  arc A10 centre (25.8, -25.2) radius 0.4 clockwise from (25.8, -24.8) to (26.2, -25.2)
  arc A11 centre (25.8, -39.8) radius 0.4 clockwise from (26.2, -39.8) to (25.8, -40.2)
  arc A12 centre (22.2, -39.8) radius 0.4 clockwise from (22.2, -40.2) to (21.8, -39.8)
  arc A13 centre (52.2, -25.2) radius 0.4 clockwise from (51.8, -25.2) to (52.2, -24.8)
  arc A14 centre (55.8, -25.2) radius 0.4 clockwise from (55.8, -24.8) to (56.2, -25.2)
  arc A15 centre (55.8, -39.8) radius 0.4 clockwise from (56.2, -39.8) to (55.8, -40.2)
  arc A16 centre (52.2, -39.8) radius 0.4 clockwise from (52.2, -40.2) to (51.8, -39.8)
  arc A17 centre (7.2, -24.8) radius 0.4 clockwise from (7.2, -25.2) to (6.8, -24.8)
  arc A18 centre (7.2, -10.2) radius 0.4 clockwise from (6.8, -10.2) to (7.2, -9.8)
  arc A19 centre (10.8, -10.2) radius 0.4 clockwise from (10.8, -9.8) to (11.2, -10.2)
  arc A20 centre (10.8, -24.8) radius 0.4 clockwise from (11.2, -24.8) to (10.8, -25.2)
  arc A21 centre (37.2, -10.2) radius 0.4 clockwise from (36.8, -10.2) to (37.2, -9.8)
  arc A22 centre (40.8, -10.2) radius 0.4 clockwise from (40.8, -9.8) to (41.2, -10.2)
  arc A23 centre (40.8, -24.8) radius 0.4 clockwise from (41.2, -24.8) to (40.8, -25.2)
  arc A24 centre (37.2, -24.8) radius 0.4 clockwise from (37.2, -25.2) to (36.8, -24.8)
  horizontal L29
  vertical L30
  horizontal L31
  vertical L32
extrude "Extrusion37" add sketch "Skizze28" profile of L29 L30 L31 L32 along normal blind 2.3
extrude "Extrusion38" add of existing geometry blind 2
extrude "Extrusion39" add of existing geometry blind 1
extrude "Extrusion40" add of existing geometry blind 1
fillet "Abrundung30" radius 0.2
delete_face "Fläche löschen39"
delete_face "Fläche löschen40"
delete_face "Fläche löschen41"
offset_faces "Flächen versetzen5" distance 1
sketch "Skizze29" plane through (0, 0, 3) normal (0, 0, 1) x axis (-1, 0, 0)
  line L1 (-61.1127, -44.1) -> (-0.1, -44.1)
  line L2 (-61.1, -48) -> (-61.1, -44.2)
  line L3 (-0.5, -48) -> (-61.1, -48)
  line L4 (0, -44.0732) -> (0, -47.5)
  line L5 (-63.5, -48) -> (-3, -48)
  line L6 (-63.5, -46.2) -> (-63.5, -48)
  line L7 (-3, -46.2) -> (-63.5, -46.2)
  line L8 (-3, -48) -> (-3, -46.2)
  arc A1 centre (-61.5, -44.2) radius 0.4 clockwise from (-61.1127, -44.1) to (-61.1, -44.2)
  arc A2 centre (-0.5, -47.5) radius 0.5 clockwise from (0, -47.5) to (-0.5, -48)
  arc A3 centre (-0.1, -43.9) radius 0.2 clockwise from (0, -44.0732) to (-0.1, -44.1)
  point P12 (-3, -48)
  point P15 (-3, -46.2)
  horizontal L5
  vertical L6
  horizontal L7
  vertical L8
  coincident L3 P12
  dimension "d205" distance P12 P15 = 1.8
extrude "Extrusion41" add sketch "Skizze29" profile of L2 L3 L5 L7 L8 along normal blind 5
delete_face "Fläche löschen42"
delete_face "Fläche löschen43"
extrude "Extrusion42" add of existing geometry blind 0.4
offset_faces "Flächen versetzen6" distance 0.4
offset_faces "Flächen versetzen7" distance 0.4
fillet "Abrundung31" radius 0.2
fillet "Abrundung32" radius 0.1
fillet "Abrundung33" radius 0.2
fillet "Abrundung34" radius 0.2
fillet "Abrundung35" radius 0.2
delete_face "Fläche löschen44"
fillet "Abrundung36" radius 0.2
fillet "Abrundung37" radius 0.2
fillet "Abrundung38" radius 0.2
delete_face "Fläche löschen45"
delete_face "Fläche löschen46"
delete_face "Fläche löschen47"
fillet "Abrundung39" radius 0.2
delete_face "Fläche löschen48"
fillet "Abrundung40" radius 0.2
delete_face "Fläche löschen49"
fillet "Abrundung41" radius 0.1
delete_face "Fläche löschen50"
fillet "Abrundung42" radius 0.1
delete_face "Fläche löschen51"
fillet "Abrundung43" radius 0.1
delete_face "Fläche löschen52"
fillet "Abrundung44" radius 0.1
offset_faces "Flächen versetzen8" distance -0.5
delete_face "Fläche löschen53"
offset_faces "Flächen versetzen9" distance -0.5
fillet "Abrundung45" radius 0.2
offset_faces "Flächen versetzen10" distance -0.5
offset_faces "Flächen versetzen11" distance -0.9
offset_faces "Flächen versetzen12" distance -0.9
offset_faces "Flächen versetzen13" distance -0.3
hole "Bohrung1" HoleDepth 15 HoleDiameter 3 TipAngle 180 CSDiameter 6 CSAngle 90
extrude "Extrusion5" cut sketch "Skizze7" profile of L5 L6 L7 L8 against normal blind 5.345 bodies "Teensy (1)"
fillet "Abrundung6" radius 0.2
extrude "Extrusion2" new body blind 11
fillet "Abrundung1" radius 0.7
base_feature "Basiselement" bodies "Teensy 4.1"
sketch "Skizze4" plane through (0, 0, 0) normal (0, 0, 1) x axis (1, 0, 0)
  line L1 (47, 19) -> (-36, 19)
  line L2 (47, -25) -> (47, 19)
  line L3 (-36, -25) -> (47, -25)
  line L4 (-36, 19) -> (-36, -25)
  horizontal L1
  vertical L2
  horizontal L3
  vertical L4
extrude "Extrusion1" cut sketch "Skizze4" along normal blind 5 bodies "Teensy 4.1 (1)", "Teensy 4.1 (2)", "Teensy 4.1 (3)", "Teensy 4.1 (4)", "Teensy 4.1 (5)", "Teensy 4.1 (6)", "Teensy 4.1 (7)", "Teensy 4.1 (8)"
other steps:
derived_base_feature "Abgeleitetes Basiselement" bodies "Teensy 4.1"
named bodies: "Teensy 4.1", "Teensy 4.1 (1)", "Teensy 4.1 (2)", "Teensy 4.1 (3)", "Teensy 4.1 (4)", "Teensy 4.1 (5)", "Teensy 4.1 (6)", "Teensy 4.1 (7)", "Teensy 4.1 (8)", "Teensy 4.1 (9)", "Teensy 4.1 (10)", "Teensy 4.1 (11)", "Teensy 4.1 (12)", "Teensy 4.1 (13)", "Teensy 4.1 (14)", "Teensy 4.1 (15)", "Teensy 4.1 (16)", "Teensy 4.1 (17)", "Teensy 4.1 (18)", "Teensy 4.1 (19)", "Teensy 4.1 (20)", "Teensy 4.1 (21)", "Teensy 4.1 (22)", "Teensy 4.1 (23)", "Teensy 4.1 (24)", "Teensy 4.1 (25)", "Teensy 4.1 (26)", "Teensy 4.1 (27)", "Teensy 4.1 (28)", "Teensy 4.1 (29)", "Teensy 4.1 (30)", "Teensy 4.1 (31)", "Teensy 4.1 (32)", "Teensy 4.1 (33)", "Teensy 4.1 (34)", "Teensy 4.1 (35)", "Unterteil", "Deckel", "Teensy (1)"

design "Teensy 4.1 Modell"
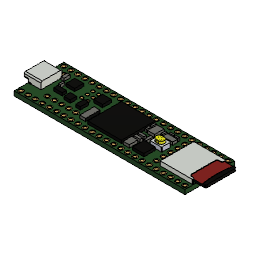
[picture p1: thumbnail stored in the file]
description: STEP AP214
part number: Teensy_4.1_Assembly_simplified
base_feature "Basiselement"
